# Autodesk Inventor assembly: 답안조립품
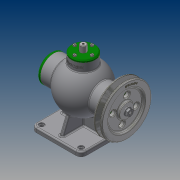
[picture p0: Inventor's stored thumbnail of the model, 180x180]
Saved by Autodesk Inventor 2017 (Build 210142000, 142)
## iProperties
Part Number: 답안조립품
Material: 일반
Document SubType Name: Assembly
Designer: 13
Author: 13
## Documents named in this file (19)
- C:\Users\13\Desktop\480414V1003\답안조립품.iam
- C:\Users\13\Desktop\480414V1003\본체.ipt
- C:\Users\13\Desktop\480414V1003\V-벨트풀리.ipt
- C:\Users\13\Desktop\480414V1003\너트 M8.ipt
- C:\Users\13\Desktop\480414V1003\뒤커버.ipt
- C:\Users\13\Desktop\480414V1003\멈춤링 15x1.ipt
- C:\Users\13\Desktop\480414V1003\멈춤링 35x1.6.ipt
- 멈춤링 35x1.6.ipt
- C:\Users\13\Desktop\480414V1003\베어링 6202.ipt
- 베어링 6202.ipt
- C:\Users\13\Desktop\480414V1003\볼트 M4x12.ipt
- C:\Users\13\Desktop\480414V1003\볼트 M4x16.ipt
- C:\Users\13\Desktop\480414V1003\부시.ipt
- C:\Users\13\Desktop\480414V1003\상부커버.ipt
- C:\Users\13\Desktop\480414V1003\슬라이드.ipt
- C:\Users\13\Desktop\480414V1003\앞커버.ipt
- C:\Users\13\Desktop\480414V1003\오일 실 15 30 7.ipt
- C:\Users\13\Desktop\480414V1003\키 4x4x12.ipt
- C:\Users\13\Desktop\480414V1003\편심축.ipt
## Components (1 placed, 1 different names)
1. V-벨트풀리:1 — 플러쉬:1
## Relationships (1: Flush 1)
- 플러쉬:1 [Flush]: V-벨트풀리:1
